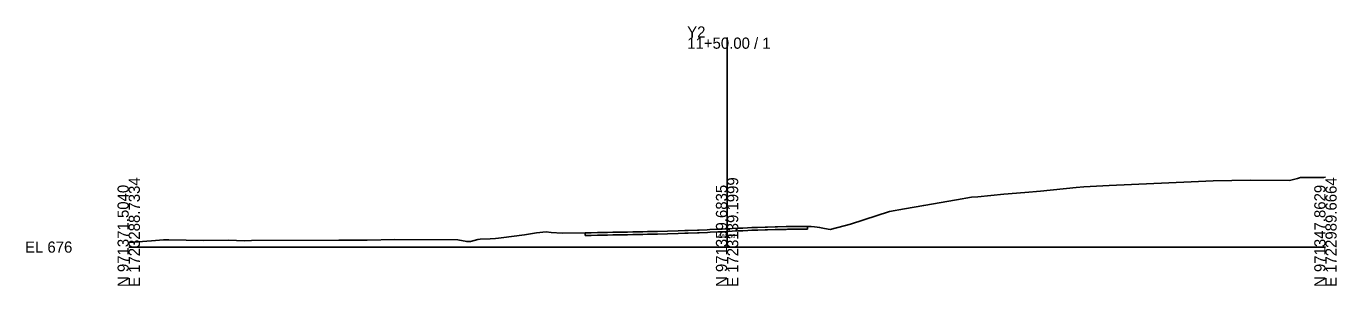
# Model space of a CAD drawing. Extents: x -26 to 303, y -10 to 3067.
# Drawn here: x -25.7 to 302.8, y 1490.3 to 1555.3 of the extents above; entities that cross this region are included whole.
import ezdxf

# ---------------------------------------------------------------- set-up
doc = ezdxf.new("R2010")
doc.units = 0
for name, color, linetype in [('Default', 7, 'Continuous'), ('Exist 6 AWG with gnd feeder circuit', 7, 'Continuous'), ('Exist 6 AWG with gnd feeder circuit in conduit', 7, 'Continuous'), ('Prop DSN Text', 7, 'Continuous')]:
    doc.layers.add(name, color=color, linetype=linetype)

msp = doc.modelspace()

# ---------------------------------------------------------------- linework, layer by layer
at = {"layer": 'Exist 6 AWG with gnd feeder circuit'}
for p, q in [((170.16, 1505.19), (170.16, 1504.52)), ((114.44, 1503.55), (114.44, 1502.89))]:
    msp.add_line(p, q, dxfattribs=at)
for points in [[(0, 1501.15), (5.72, 1501.56), (8.72, 1501.81), (9.45, 1501.81), (10.09, 1501.81), (18.75, 1501.68), (25.07, 1501.7), (28.95, 1501.59), (30.78, 1501.65), (52.65, 1501.74), (53.86, 1501.74), (59.81, 1501.75), (66.74, 1501.92), (82.5, 1501.86), (84.73, 1501.37), (85.67, 1501.37), (87.5, 1501.88), (88.1, 1501.97), (90.61, 1502.09), (91.95, 1502.16), (92.68, 1502.24), (93.36, 1502.32), (99.2, 1503.04), (102.2, 1503.57), (104.64, 1503.83), (105.87, 1503.69), (108.64, 1503.46), (114.44, 1503.55), (115.16, 1503.58), (115.89, 1503.59), (117.52, 1503.63), (118.51, 1503.65), (120.03, 1503.69), (121.33, 1503.72), (122.54, 1503.74), (123.96, 1503.76), (125.04, 1503.77), (126.34, 1503.79), (127.32, 1503.8), (128.89, 1503.84), (130.03, 1503.87), (130.6, 1503.88), (132.53, 1503.94), (135.04, 1504.01), (137.7, 1504.09), (139.39, 1504.14), (140.23, 1504.17), (142.58, 1504.23), (143, 1504.25), (145.04, 1504.35), (145.7, 1504.38), (147.62, 1504.46), (148.79, 1504.52), (150.25, 1504.59), (151.25, 1504.64), (152.62, 1504.71), (153.92, 1504.77), (155.14, 1504.83), (156.19, 1504.88), (157.65, 1504.94), (159.51, 1505), (160.15, 1505.02), (162.04, 1505.07), (162.63, 1505.08), (164.78, 1505.12), (165.14, 1505.13), (165.44, 1505.13), (167.64, 1505.15), (169.34, 1505.18), (170.16, 1505.19), (171.04, 1505.17), (171.94, 1505.06), (172.57, 1504.98), (173.2, 1504.95), (174.38, 1504.68), (175.82, 1504.41), (179.34, 1505.35), (180.93, 1505.76), (184.24, 1506.87), (190.73, 1508.92), (194.51, 1509.62), (199.3, 1510.46), (207.52, 1511.85), (211.24, 1512.48), (212.84, 1512.62), (219.37, 1513.3), (224.61, 1513.68), (228.58, 1514.04), (237.5, 1514.92), (239.43, 1515.12), (245.77, 1515.44), (266.34, 1516.39), (271.82, 1516.6), (281.23, 1516.74), (290.97, 1516.67), (293.01, 1517.21), (293.77, 1517.41), (294.95, 1517.42), (299.61, 1517.48), (300, 1517.5)], [(114.44, 1502.89), (115.17, 1502.91), (115.91, 1502.93), (117.54, 1502.96), (118.53, 1502.99), (120.05, 1503.02), (121.35, 1503.05), (122.55, 1503.08), (123.96, 1503.09), (125.05, 1503.1), (126.35, 1503.12), (127.34, 1503.13), (128.9, 1503.17), (130.05, 1503.2), (130.61, 1503.22), (132.55, 1503.27), (135.06, 1503.34), (137.72, 1503.42), (139.41, 1503.48), (140.24, 1503.5), (142.6, 1503.56), (143.04, 1503.58), (145.07, 1503.68), (145.73, 1503.71), (147.66, 1503.8), (148.82, 1503.85), (150.28, 1503.93), (151.28, 1503.98), (152.65, 1504.04), (153.95, 1504.11), (155.17, 1504.17), (156.22, 1504.21), (157.67, 1504.27), (159.53, 1504.34), (160.17, 1504.36), (162.05, 1504.4), (162.64, 1504.41), (164.79, 1504.45), (165.15, 1504.46), (165.45, 1504.46), (167.65, 1504.49), (169.35, 1504.51), (170.16, 1504.52)]]:
    msp.add_lwpolyline(points, dxfattribs=at)
at = {"layer": 'Prop DSN Text'}
for p, q in [((150, 1500), (150, 1552.5)), ((0, 1500), (150, 1500)), ((150, 1500), (300, 1500))]:
    msp.add_line(p, q, dxfattribs=at)

# ---------------------------------------------------------------- texts
at = {"layer": 'Default'}
msp.add_text('-', height=0.0001, dxfattribs=at).set_placement((0, 1500))
at = {"layer": 'Exist 6 AWG with gnd feeder circuit in conduit'}
msp.add_text('680.58', height=1, dxfattribs=at).set_placement((147.83, 1502.29))
at = {"layer": 'Prop DSN Text'}
for s, p in [('Y2', (140, 1552.5)), ('11+50.00 / 1', (140, 1549.7)), ('EL 676', (-26, 1498.6))]:
    msp.add_text(s, height=2.8, dxfattribs=at).set_placement(p)
for s, p in [('N 971371.5040', (0, 1490)), ('E 1723288.7334', (2.8, 1490)), ('N 971359.6835', (150, 1490)), ('E 1723139.1999', (152.8, 1490)), ('N 971347.8629', (300, 1490)), ('E 1722989.6664', (302.8, 1490))]:
    msp.add_text(s, height=2.8, rotation=90, dxfattribs=at).set_placement(p)

doc.saveas('drawing.dxf')
